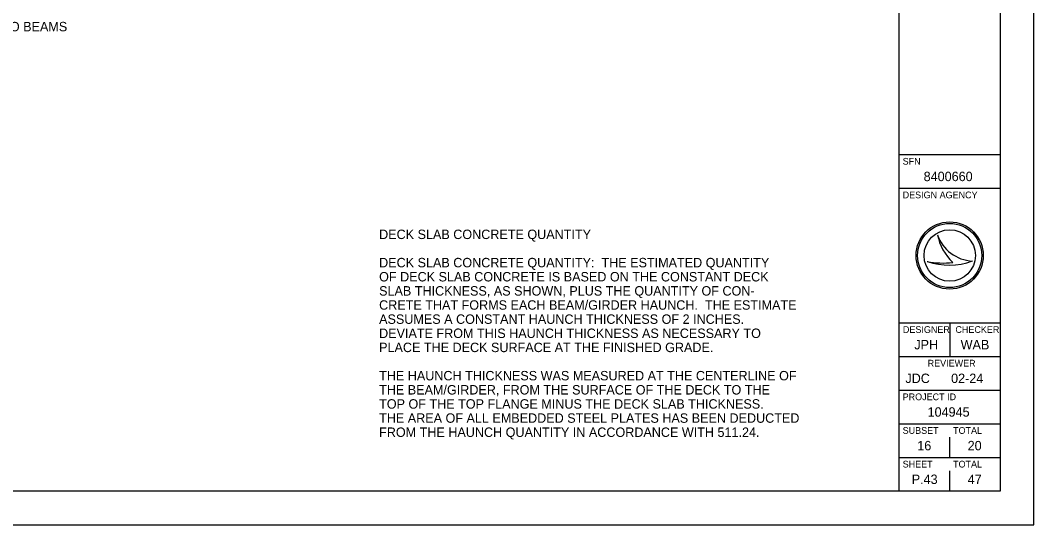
# Model space of a CAD drawing. Extents: x -86 to 68, y -5 to 62.
# Drawn here: x 37.85 to 68, y 0 to 14.99 of the extents above; entities that cross this region are included whole.
import ezdxf

# ---------------------------------------------------------------- set-up
doc = ezdxf.new("R2010")
doc.units = 0
for name, color, linetype in [('SH_Border', 7, 'Continuous'), ('SH_Cut_Line', 7, 'Continuous'), ('SH_Data', 7, 'Continuous'), ('TX_P_1', 7, 'Continuous'), ('TX_P_Misc', 7, 'Continuous')]:
    doc.layers.add(name, color=color, linetype=linetype)

msp = doc.modelspace()

# ---------------------------------------------------------------- linework, layer by layer
at = {"layer": 'SH_Border'}
for p, q in [((64, 1), (64, 43)), ((64, 11), (67, 11)), ((64, 10), (67, 10)), ((64, 6), (67, 6)), ((65.5, 6), (65.5, 5)), ((64, 5), (67, 5)), ((64, 4), (67, 4)), ((64, 3), (67, 3)), ((64, 2), (67, 2))]:
    msp.add_line(p, q, dxfattribs=at)
msp.add_lwpolyline([(3, 43), (67, 43), (67, 1), (3, 1)], close=True, dxfattribs=at)
at = {"layer": 'SH_Cut_Line'}
msp.add_lwpolyline([(0, 0), (68, 0), (68, 44), (0, 44)], close=True, dxfattribs=at)
at = {"layer": 'SH_Data'}
for p, q in [((65.135, 8.619), (65.135, 8.619)), ((65.5, 8), (65.5, 8)), ((64.834, 7.819), (64.834, 7.819)), ((66.175, 7.837), (66.175, 7.837)), ((65.5, 2), (65.5, 2.6)), ((65.5, 1), (65.5, 1.6)), ((64.75, 1.35), (64.75, 1.35))]:
    msp.add_line(p, q, dxfattribs=at)
for radius in [1, 0.954, 0.954, 0.764]:
    msp.add_circle((65.5, 8), radius, dxfattribs=at)
for centre, radius, start, end in [((66.232, 8.995), 1.16, 198.9257, 198.9319), ((66.693, 8.94), 1.591, 191.6379, 191.6421), ((66.232, 8.995), 1.16, 198.9319, 267.1657), ((66.693, 8.94), 1.591, 191.6421, 226.0947), ((65.479, 9.74), 2.026, 251.4576, 290.0832), ((65.296, 10.309), 2.532, 259.4964, 259.4995), ((65.479, 9.74), 2.026, 251.4527, 251.4576), ((65.296, 10.309), 2.532, 259.4995, 276.6672)]:
    msp.add_arc(centre, radius, start, end, dxfattribs=at)

# ---------------------------------------------------------------- texts
for s, height, p in [('SFN', 0.2, (64.1, 10.7)), ('8400660', 0.28, (64.725, 10.21)), ('DESIGN AGENCY', 0.2, (64.1, 9.7)), ('DESIGNER', 0.2, (64.108, 5.7)), ('CHECKER', 0.2, (65.67, 5.7)), ('JPH', 0.28, (64.447, 5.21)), ('WAB', 0.28, (65.826, 5.21)), ('REVIEWER', 0.2, (64.844, 4.7)), ('JDC', 0.28, (64.182, 4.21)), ('02-24', 0.28, (65.542, 4.21)), ('PROJECT ID', 0.2, (64.1, 3.7)), ('104945', 0.28, (64.842, 3.21)), ('SUBSET', 0.2, (64.1, 2.7)), ('TOTAL', 0.2, (65.6, 2.7)), ('16', 0.28, (64.535, 2.21)), ('20', 0.28, (66.034, 2.21)), ('SHEET', 0.2, (64.1, 1.7)), ('TOTAL', 0.2, (65.6, 1.7)), ('P.43', 0.28, (64.37, 1.21)), ('47', 0.28, (66.037, 1.21))]:
    msp.add_text(s, height=height, dxfattribs=at).set_placement(p)
at = {"layer": 'TX_P_1'}
for s, p in [('SEE SHEET 13 OF 20 FOR SPACING NORMAL TO BEAMS', (29.05, 14.662)), ('DECK SLAB CONCRETE QUANTITY', (48.524, 8.489)), ('DECK SLAB CONCRETE QUANTITY:  THE ESTIMATED QUANTITY', (48.524, 7.649)), ('OF DECK SLAB CONCRETE IS BASED ON THE CONSTANT DECK', (48.524, 7.229)), ('SLAB THICKNESS, AS SHOWN, PLUS THE QUANTITY OF CON-', (48.524, 6.809)), ('CRETE THAT FORMS EACH BEAM/GIRDER HAUNCH.  THE ESTIMATE', (48.524, 6.389)), ('DEVIATE FROM THIS HAUNCH THICKNESS AS NECESSARY TO', (48.524, 5.549)), ('PLACE THE DECK SURFACE AT THE FINISHED GRADE.', (48.524, 5.129)), ('THE HAUNCH THICKNESS WAS MEASURED AT THE CENTERLINE OF', (48.524, 4.289)), ('THE BEAM/GIRDER, FROM THE SURFACE OF THE DECK TO THE', (48.524, 3.869)), ('TOP OF THE TOP FLANGE MINUS THE DECK SLAB THICKNESS.', (48.524, 3.449)), ('THE AREA OF ALL EMBEDDED STEEL PLATES HAS BEEN DEDUCTED', (48.524, 3.029)), ('FROM THE HAUNCH QUANTITY IN ACCORDANCE WITH 511.24.', (48.524, 2.609))]:
    msp.add_text(s, height=0.28, dxfattribs=at).set_placement(p)
at = {"layer": 'TX_P_Misc'}
msp.add_text('ASSUMES A CONSTANT HAUNCH THICKNESS OF 2 INCHES.', height=0.28, dxfattribs=at).set_placement((48.524, 5.969))

doc.saveas('drawing.dxf')
